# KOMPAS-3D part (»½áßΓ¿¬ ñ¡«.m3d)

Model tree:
1. Эскиз:1
2. Операция выдавливания:1
     Расстояние 1 = 2
3. Эскиз:2
4. Операция выдавливания:2
     Расстояние 1 = 2
5. Эскиз:3
6. Вырезать элемент выдавливания:1
     Расстояние 1 = 10
7. Эскиз:4
8. Вырезать элемент выдавливания:2
     Расстояние 1 = 4

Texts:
  Полипропилен  ГОСТ 26996-86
